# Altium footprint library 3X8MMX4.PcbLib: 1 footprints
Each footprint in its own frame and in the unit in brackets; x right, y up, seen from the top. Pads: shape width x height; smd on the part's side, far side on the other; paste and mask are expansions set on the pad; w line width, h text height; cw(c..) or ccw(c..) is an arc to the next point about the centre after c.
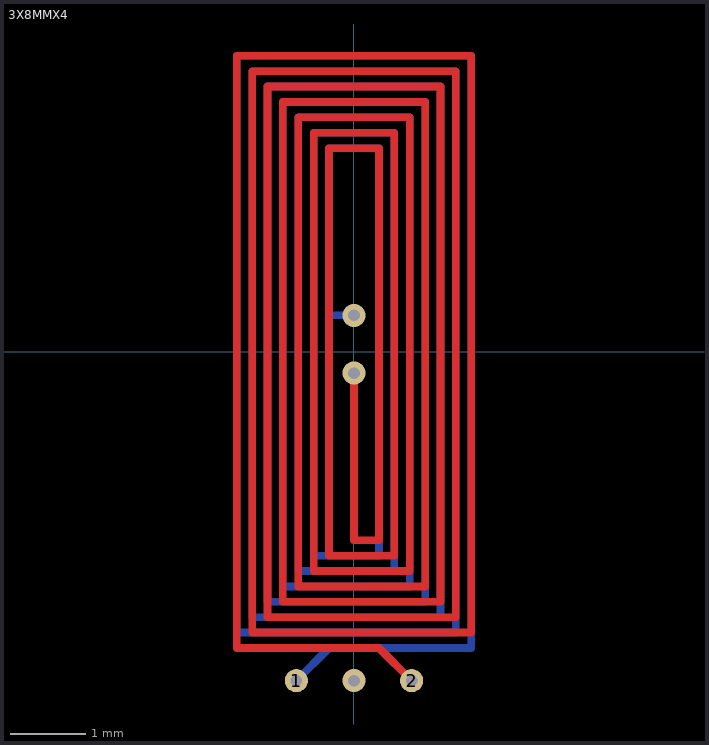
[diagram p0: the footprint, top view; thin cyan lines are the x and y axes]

## 3X8MMX4 [mil]
pads (2):
  round 12 hole 6: 1(-30,-171) 2(30,-171)
via 0,-171 diameter 12 hole 6
via 0,19 diameter 12 hole 6
via 0,-11 diameter 12 hole 6
Top Layer:
  lines w4: 0,-11 0,-98 13,-98 13,106 -13,106 -13,-106 21,-106 21,114 -21,114 -21,-114 29,-114 29,122 -29,122 -29,-122 37,-122 37,130 -37,130 -37,-130 45,-130 45,138 -45,138 -45,-138 53,-138 53,146 -53,146 -53,-146 61,-146 61,154 -61,154 -61,-154 0,-154 11,-154 13,-154 30,-171
Mid-Layer 1:
  lines w4: 0,-171 0,-154 61,-154 61,154 -61,154 -61,-146 53,-146 53,146 -53,146 -53,-138 45,-138 45,138 -45,138 -45,-130 37,-130 37,130 -37,130 -37,-122 29,-122 29,122 -29,122 -29,-114 21,-114 21,114 -21,114 -21,-106 13,-106 13,106 -13,106 -13,-98 0,-98 0,-11
Mid-Layer 2:
  lines w4: 0,-171 0,-154 -61,-154 -61,154 61,154 61,-146 -53,-146 -53,146 53,146 53,-138 -45,-138 -45,138 45,138 45,-130 -37,-130 -37,130 37,130 37,-122 -29,-122 -29,122 29,122 29,-114 -21,-114 -21,114 21,114 21,-106 -13,-106 -13,106 13,106 13,19 0,19
Bottom Layer:
  lines w4: -30,-171 -13,-154 -11,-154 0,-154 61,-154 61,154 -61,154 -61,-146 53,-146 53,146 -53,146 -53,-138 45,-138 45,138 -45,138 -45,-130 37,-130 37,130 -37,130 -37,-122 29,-122 29,122 -29,122 -29,-114 21,-114 21,114 -21,114 -21,-106 13,-106 13,106 -13,106 -13,19 0,19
